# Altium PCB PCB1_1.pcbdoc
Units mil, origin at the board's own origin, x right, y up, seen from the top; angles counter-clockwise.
Board outline 1663.74 x 2242.19 mil, 2 copper layers (Top Layer, Bottom Layer); 33 components, 26 nets, 113 pads, 266 vias.
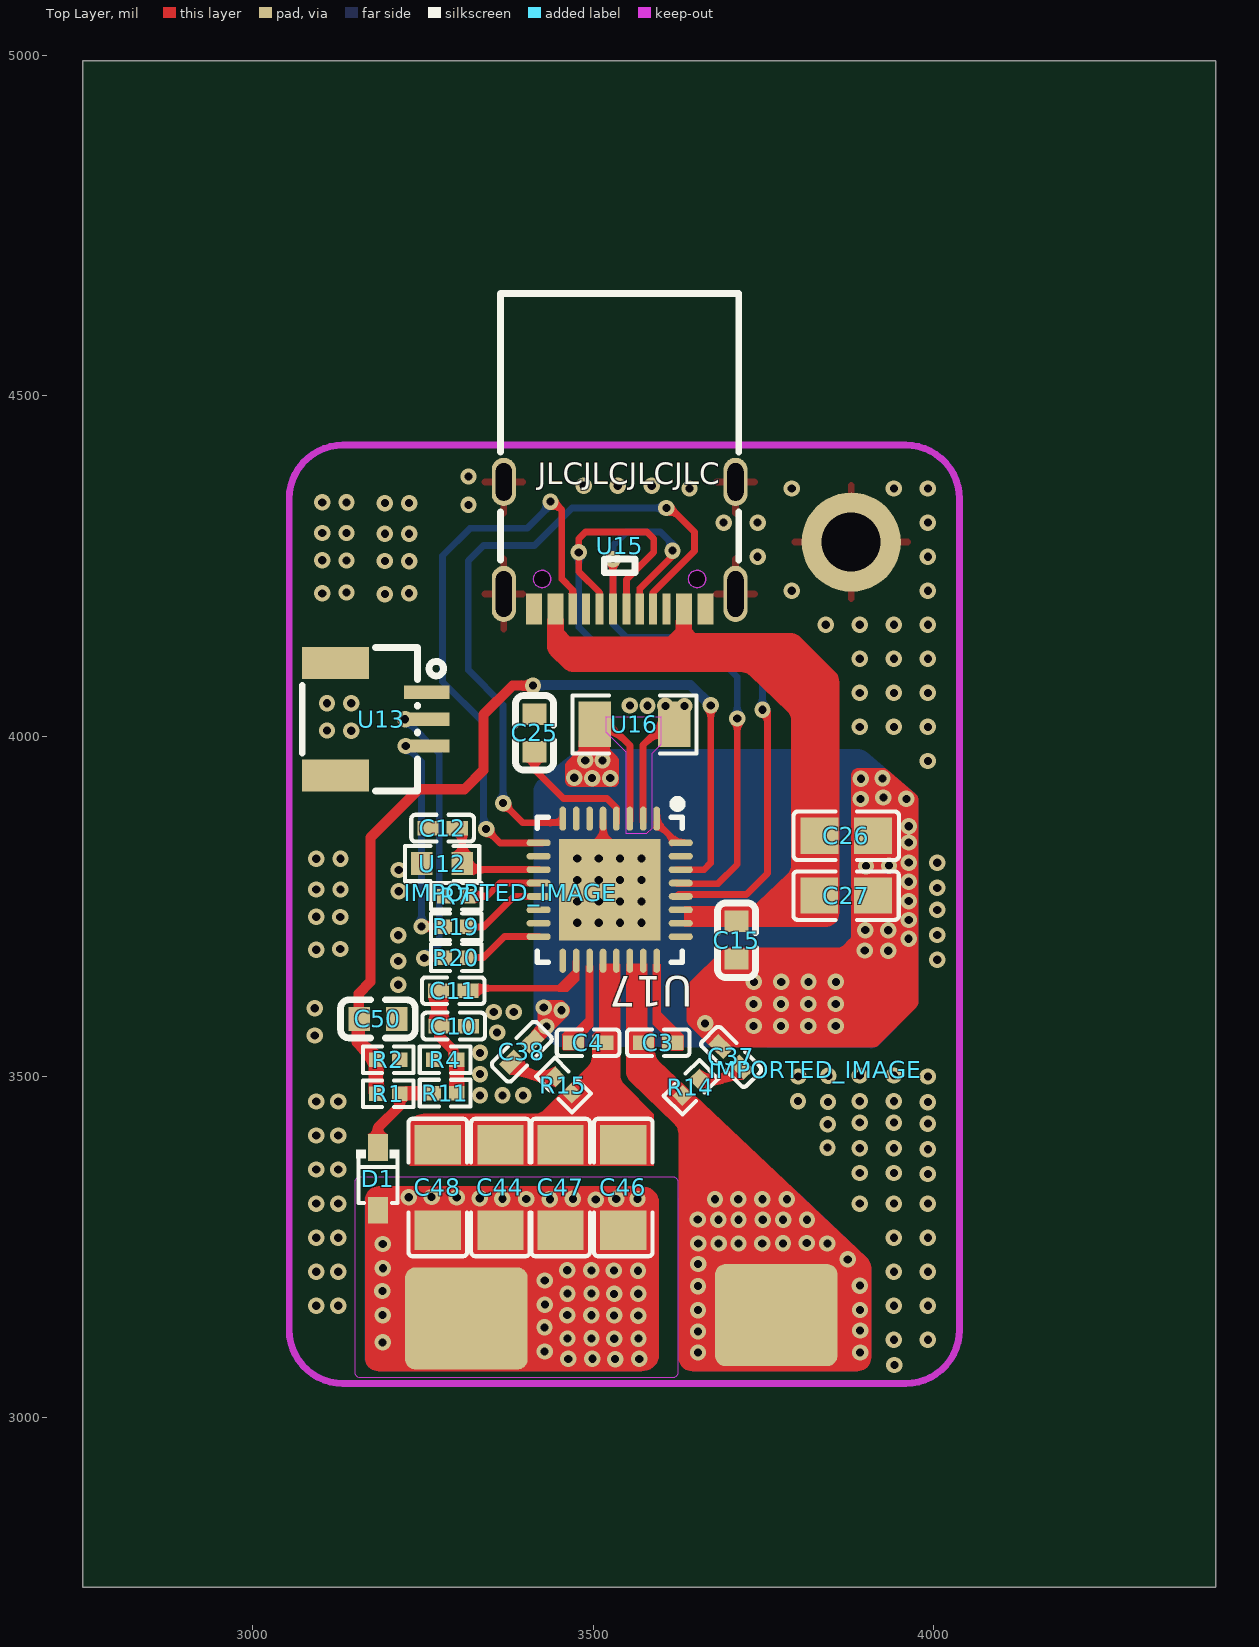
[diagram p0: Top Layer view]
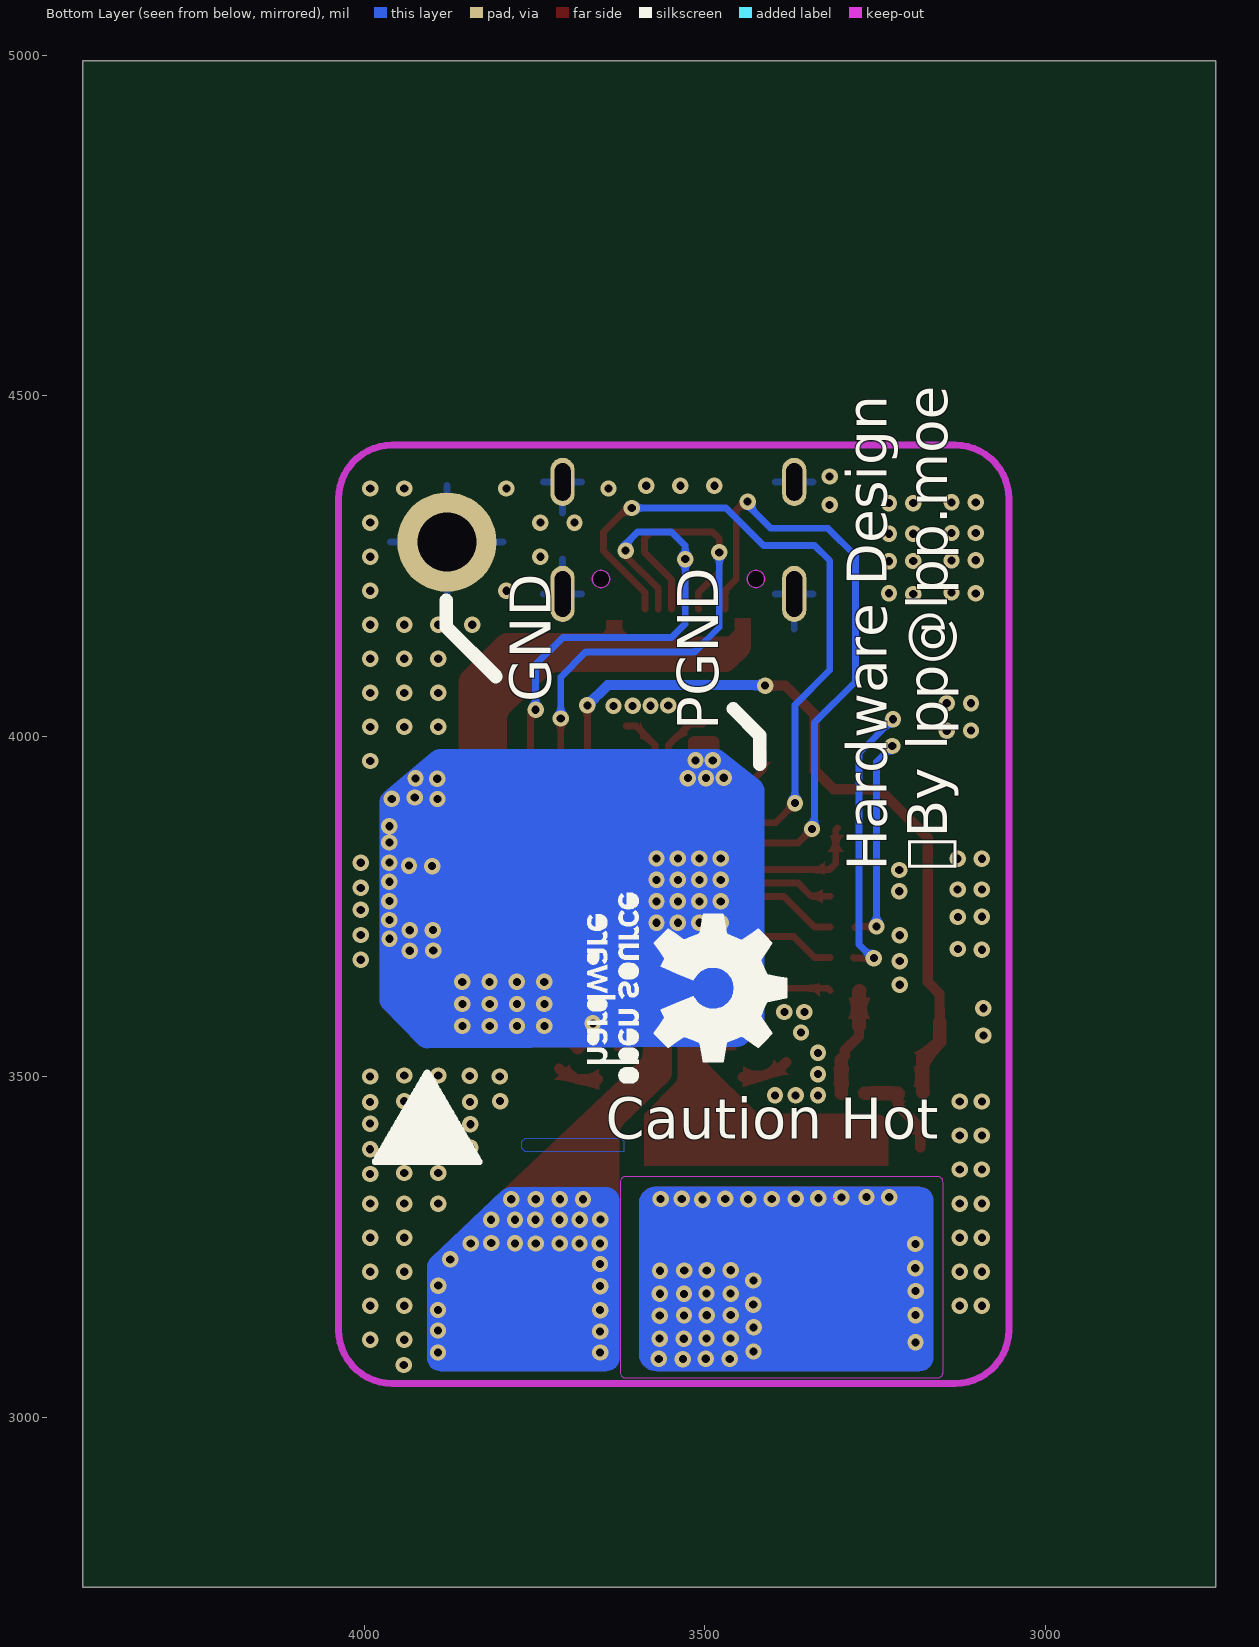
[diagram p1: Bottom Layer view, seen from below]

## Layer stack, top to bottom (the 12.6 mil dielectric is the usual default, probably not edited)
Top Layer: signal copper (thickness not stored)
Dielectric: dielectric 12.6, FR-4, Dk 4.8
Bottom Layer: signal copper (thickness not stored)

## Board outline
4413.74,2750 2750,2750 2750,4992.19 4413.74,4992.19

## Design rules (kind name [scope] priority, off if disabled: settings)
BoardOutlineClearance copperThickness1oz [All] p0: genericclearance=10 ignorepadtopadclearanceinfootprint=FALSE except(0: Arc-SplitContinuation Track-SplitContinuation SMDPad-SplitContinuation THPad-SplitContinuation Via-SplitContinuation Fill-SplitContinuation Poly-SplitContinuation Region-SplitContinuation Text-SplitContinuation; 6: Track-CutoutEdge SMDPad-CutoutEdge THPad-CutoutEdge Via-CutoutEdge Region-CutoutEdge; 11.8: Track-OutlineEdge SMDPad-OutlineEdge THPad-OutlineEdge Via-OutlineEdge Fill-OutlineEdge Region-OutlineEdge Poly-OutlineEdge Text-OutlineEdge Fill-CutoutEdge)
BoardOutlineClearance copperThickness2oz [All] p0: genericclearance=10 ignorepadtopadclearanceinfootprint=FALSE except(0: Arc-SplitContinuation Track-SplitContinuation SMDPad-SplitContinuation THPad-SplitContinuation Via-SplitContinuation Fill-SplitContinuation Poly-SplitContinuation Region-SplitContinuation Text-SplitContinuation; 6: Track-CutoutEdge SMDPad-CutoutEdge THPad-CutoutEdge Via-CutoutEdge Region-CutoutEdge; 11.8: Track-OutlineEdge SMDPad-OutlineEdge THPad-OutlineEdge Via-OutlineEdge Fill-OutlineEdge Region-OutlineEdge Poly-OutlineEdge Text-OutlineEdge Fill-CutoutEdge)
Clearance copperThickness1oz [(InNet('GND') OR InNet('VDET') OR InNet('LX2') OR InNet('LX1') OR InNet('PAD1') OR InNet('V_DECODE') OR InNet('VBUS') OR InNet('PGND') OR InNet('DP') OR InNet('DN') OR InNet('DEBUG') OR InNet('CC2') OR InNet('CC1') OR InNet('$1N1645') OR InNet('$1N1658') OR InNet('$1N1611') OR InNet('$1N1640') OR InNet('$1N1651') OR InNet('$1N1650') OR InNet('$1N1648') OR InNet('$1N1649') OR InNet('$1N1655') OR InNet('$1N6577') OR InNet('$1N6953') OR InNet('$1N16061') OR InNet('$1N16063'))] p1: gap=7 ignorepadtopadclearanceinfootprint=FALSE except(4: Track-Track; 6: Track-SMDPad SMDPad-SMDPad Track-THPad SMDPad-THPad THPad-THPad Track-Via SMDPad-Via THPad-Via Via-Via SMDPad-Fill THPad-Fill Via-Fill Fill-Fill Track-Region SMDPad-Region THPad-Region Via-Region Region-Region Track-Poly SMDPad-Poly THPad-Poly Via-Poly Fill-Poly Region-Poly Poly-Poly Track-Text SMDPad-Text THPad-Text Via-Text Fill-Text Region-Text Poly-Text Text-Text; 6.9: Track-Hole SMDPad-Hole THPad-Hole Via-Hole Fill-Hole Region-Hole Poly-Hole Text-Hole Sheet-Hole; 11.8: Track-Fill Fill-Region Track-Sheet SMDPad-Sheet THPad-Sheet Via-Sheet Fill-Sheet Region-Sheet Poly-Sheet Text-Sheet)
Clearance copperThickness2oz [All] p1: gap=7 ignorepadtopadclearanceinfootprint=FALSE except(6: Track-SMDPad SMDPad-SMDPad Track-THPad SMDPad-THPad THPad-THPad Track-Via SMDPad-Via THPad-Via Via-Via SMDPad-Fill THPad-Fill Via-Fill Fill-Fill Track-Region SMDPad-Region THPad-Region Via-Region Region-Region Track-Poly SMDPad-Poly THPad-Poly Via-Poly Fill-Poly Region-Poly Poly-Poly Track-Text SMDPad-Text THPad-Text Via-Text Fill-Text Region-Text Poly-Text Text-Text; 6.9: Track-Hole SMDPad-Hole THPad-Hole Via-Hole Fill-Hole Region-Hole Poly-Hole Text-Hole Sheet-Hole; 8: Track-Track; 11.8: Track-Fill Fill-Region Track-Sheet SMDPad-Sheet THPad-Sheet Via-Sheet Fill-Sheet Region-Sheet Poly-Sheet Text-Sheet)
DiffPairsRouting differentialPair [All] p1: maxuncoupledlength=10 minlimit=5.9843 maxlimit=5.9843 mostfreqgap=5.9843 toplayer_minwidth=5 toplayer_prefwidth=10 toplayer_maxwidth=100 bottomlayer_minwidth=5 bottomlayer_prefwidth=10 bottomlayer_maxwidth=100
PasteMaskExpansion pasteMaskExpansion [All] p1: expansion=0
PlaneConnect innerPlane [All] p1: planeconnectstyle=Relief reliefexpansion=20 reliefentries=4 reliefconductorwidth=10 reliefairgap=10
PolygonConnect copperRegion [All] p1: connectstyle=Direct reliefentries=4 reliefconductorwidth=10 polygonreliefangle="90 Angle" airgapwidth=10
RoutingVias viaSize [All] p1: viastyle="Through Hole" holewidth=12.0078 minholewidth=11.811 maxholewidth=248.0314 width=24.0158 minwidth=19.685 maxwidth=393.7008
SolderMaskExpansion solderMaskExpansion [All] p1: useseparateexpansions=TRUE expansion=2.0079 expansionbottom=2.0079
Width copperThickness1oz [All] p1: maxlimit=100 minlimit=5 preferedwidth=10
Width copperThickness2oz [All] p1: maxlimit=100 minlimit=8 preferedwidth=10

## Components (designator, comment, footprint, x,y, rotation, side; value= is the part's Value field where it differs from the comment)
C3 "CL05B104KB54PNC" C0402 3595.31,3549.94 r180 top
C4 "CL05B104KB54PNC" C0402 3492.34,3549.89 r0 top
C10 "CC0402KRX7R9BB153" C0402 3295.08,3574.39 r180 top
C11 "CC0402KRX7R9BB153" C0402 3294.36,3626.34 r180 top
C12 "CC0402KRX7R9BB153" C0402 3278.74,3865 r180 top
C15 "CC0603KRX7R9BB104" C0603 3710.38,3700.45 r90 top
C25 "CL10A225KO8NNNC" C0603 3413.74,4005 r270 top
C26 "CL21A226MAQNNNE" C0805 3871.51,3853.83 r180 top
C27 "CL21A226MAQNNNE" C0805 3871.27,3765.98 r180 top
C37 "CC0402JRX7R9BB222" C0402 3702.44,3529.14 r135 top
C38 "CC0402JRX7R9BB222" C0402 3395.06,3536.66 r45 top
C44 "GRM31M5C1H473JA01L" C1206 3363.74,3337.35 r270 top
C46 "GRM31C5C1H104JA01L" C1206 3544.11,3337.35 r270 top
C47 "GRM31C5C1H104JA01L" C1206 3451.95,3337.35 r270 top
C48 "GRM31C5C1H104JA01L" C1206 3271.74,3337.35 r270 top
C50 "0603B222K500NT" C0603 3183.74,3585 r0 top
D1 "1N5819WS_C191023" SOD-323_L1.8-W1.3-LS2.5-RD 3183.74,3350 r270 top
IMPORTED_IMAGE "IMPORTED_IMAGE" IMPORTED_IMAGE 3379.02,3770.18 r0 top
IMPORTED_IMAGE "IMPORTED_IMAGE" IMPORTED_IMAGE 3826.97,3510.36 r0 top
R1 "0402WGF1003TCE" R0402 3198.74,3475 r0 top
R2 "0402WGF1002TCE" R0402 3198.74,3525 r180 top
R4 "0402WGF3302TCE" R0402 3282.36,3524.96 r0 top
R7 "0402WGF1003TCE" R0402 3298.74,3765 r180 top
R11 "0402WGF3301TCE" R0402 3282.36,3475.9 r0 top
R14 "0402WGF200KTCE" R0402 3643.28,3484.41 r45 top
R15 "0402WGF200KTCE" R0402 3456.27,3487.73 r135 top
R19 "0402WGF1000TCE" R0402 3298.74,3720 r0 top
R20 "0402WGF1000TCE" R0402 3298.74,3675 r0 top
U12 "KNTC0603/100KF3950" R0603 3278.05,3813.05 r0 top
U13 "WAFER-SH1.0-3PWB" CONN-SMD_3P-P1.00_WAFER-SH1.0-3PWB 3188.74,4025 r270 top
U15 "MC-121-L119" USB-C-SMD_HANBO_MC-121-L119 3538.74,4280 r180 top
U16 "FRM121WFR020TM" R1206 3560.49,4017.39 r0 top
U17 "IP6826_C2921390" QFN-32_L5.0-W5.0-P0.50-BL-EP3.8 3524.15,3774.57 r180 top

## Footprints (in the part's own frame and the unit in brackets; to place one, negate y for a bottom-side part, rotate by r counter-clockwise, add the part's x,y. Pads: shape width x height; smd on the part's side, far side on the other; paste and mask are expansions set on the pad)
C0402 [mm]
  rect 0.79x0.54 smd: 1(-0.545,0) 2(0.545,0)
  silkscreen extent -1.17,-0.5 1.17,0.5
C0603 [mm]
  rect 0.8x0.9 smd: 1(-0.7,0) 2(0.7,0)
  silkscreen extent -1.39,-0.71 1.39,0.71
C0805 [mm]
  rect 1.41x1.35 smd: 1(-1,0) 2(1,0)
  silkscreen extent -1.96,-0.9 1.96,0.9
C1206 [mm]
  rect 1.485x1.728 smd: 1(-1.593,0) 2(1.593,0)
  silkscreen extent -2.56,-1.09 2.56,1.09
CONN-SMD_3P-P1.00_WAFER-SH1.0-3PWB [mm]
  rect 0.5x1.7 smd: 1(-1,1.7) 2(0,1.7) 3(1,1.7)
  rect 1.2x2.5 smd: 4(-2.1,-1.7) 5(2.1,-1.7)
  silkscreen extent -2.68,-2.95 2.67,2.32
IMPORTED_IMAGE [mil]
QFN-32_L5.0-W5.0-P0.50-BL-EP3.8 [mm]
  oval 0.25x0.9 smd: 1(-1.75,-2.65) 2(-1.25,-2.65) 3(-0.749,-2.65) 4(-0.249,-2.65) 5(0.249,-2.65) 6(0.749,-2.65) 7(1.25,-2.65) 8(1.75,-2.65) 17(1.75,2.65) 18(1.25,2.65) 19(0.749,2.65) 20(0.249,2.65) 21(-0.249,2.65) 22(-0.749,2.65) 23(-1.25,2.65) 24(-1.75,2.65)
  oval 0.9x0.25 smd: 9(2.65,-1.75) 10(2.65,-1.25) 11(2.65,-0.749) 12(2.65,-0.249) 13(2.65,0.249) 14(2.65,0.749) 15(2.65,1.25) 16(2.65,1.75) 25(-2.65,1.75) 26(-2.65,1.25) 27(-2.65,0.749) 28(-2.65,0.249) 29(-2.65,-0.249) 30(-2.65,-0.749) 31(-2.65,-1.25) 32(-2.65,-1.75)
  rect 3.8x3.8 smd: 33(0,0)
  silkscreen extent -2.7,-3.35 2.7,2.7
R0402 [mm]
  rect 0.566x0.54 smd: 1(-0.433,0) 2(0.433,0)
  silkscreen extent -0.94,-0.5 0.94,0.5
R0603 [mil]
  rect 31.75x34.02 smd: 1(-29.66,0) 2(29.66,0)
  silkscreen extent -55,-26 55,26
R1206 [mil]
  rect 47.54x66.97 smd: 1(-58.22,0) 2(58.22,0)
  silkscreen extent -91,-42 91,42
SOD-323_L1.8-W1.3-LS2.5-RD [mm]
  rect 1x0.75 smd: 1(-1.173,0) 2(1.173,0)
  silkscreen extent -1.08,-0.8 0.9,0.8
USB-C-SMD_HANBO_MC-121-L119 [mm]
  oval 0.9x1.8 hole 0.6 slot 1.4 at 90 deg: 13(-4.32,-2.373) 13(4.32,-2.373)
  oval 0.9x2.1 hole 0.6 slot 1.7 at 90 deg: 13(-4.32,1.807) 13(4.32,1.807)
  rect 0.6x1.15 smd: A1B12(-3.2,2.372) A4B9(-2.4,2.372) B1A12(3.2,2.372) B4A9(2.4,2.372)
  rect 0.3x1.15 smd: A5(-1.25,2.372) A6(-0.25,2.372) A7(0.25,2.372) A8(1.25,2.372) B5(1.75,2.372) B6(0.75,2.372) B7(-0.75,2.372) B8(-1.75,2.372)
  Board Outline Layer circle w0.005: c2.89,1.248 r0.325
  Board Outline Layer circle w0.005: c-2.89,1.248 r0.325
  Board Outline Layer region: 2.565,1.248 2.597,1.389 2.687,1.502 2.818,1.564 2.962,1.564 3.093,1.502 3.183,1.389 3.215,1.248 3.215,1.248 3.183,1.107 3.093,0.993 2.962,0.931 2.818,0.931 2.687,0.993 2.597,1.107 2.565,1.248
  Board Outline Layer region: -3.215,1.248 -3.183,1.389 -3.093,1.502 -2.962,1.564 -2.818,1.564 -2.688,1.502 -2.597,1.389 -2.565,1.248 -2.565,1.248 -2.597,1.107 -2.688,0.993 -2.818,0.931 -2.962,0.931 -3.093,0.993 -3.183,1.107 -3.215,1.248
  Multi-Layer board cut-out: 2.565,1.248 2.597,1.389 2.687,1.502 2.818,1.564 2.962,1.564 3.093,1.502 3.183,1.389 3.215,1.248 3.215,1.248 3.183,1.107 3.093,0.993 2.962,0.931 2.818,0.931 2.687,0.993 2.597,1.107 2.565,1.248
  Multi-Layer board cut-out: -3.215,1.248 -3.183,1.389 -3.093,1.502 -2.962,1.564 -2.818,1.564 -2.688,1.502 -2.597,1.389 -2.565,1.248 -2.565,1.248 -2.597,1.107 -2.688,0.993 -2.818,0.931 -2.962,0.931 -3.093,0.993 -3.183,1.107 -3.215,1.248
  silkscreen extent -4.45,-9.4 4.44,1.02

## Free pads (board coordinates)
  rrect20% 180x150 smd: 1(3313.74,3145) 1(3768.74,3150)
  round 145.67 hole 86.61: 1(3878.74,4285)

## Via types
v1: diameter 24.02, hole 12.01, Top Layer to Bottom Layer, 266 vias

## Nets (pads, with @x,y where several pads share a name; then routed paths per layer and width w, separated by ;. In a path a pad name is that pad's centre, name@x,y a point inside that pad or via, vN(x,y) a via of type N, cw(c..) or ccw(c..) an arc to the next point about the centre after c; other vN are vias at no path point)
$1N1611: C25.2 U17.4 | length 191.8
  Top Layer w10: C25.2 3413.74,3951.14 3456.19,3908.69 3520.05,3908.69 3534.02,3894.72 U17.4@3534.02,3872.91
$1N1640: D1.1 R1.2 R11.1 | length 142
  Top Layer w15: D1.1 3183.74,3425 3215.78,3457.04 R1.2
  Top Layer w20: R1.2 3216.68,3475.9 R11.1
$1N1645: C10.2 C11.2 R4.2 R11.2 | length 161.4
  Top Layer w15: C10.2 3273.62,3559.39 3294.4,3538.6 3294.4,3529.96 R4.2
  Top Layer w20: C11.2 3273.62,3625.61 C10.2 ; R11.2 R4.2
$1N1648: R19.2 U17.13 | length 122.6
  Top Layer w10: R19.2 3338.97,3720 3383.74,3764.77 U17.13
$1N1649: R20.2 U17.16 | length 116.7
  Top Layer w10: R20.2 3338.74,3675 3369.41,3705.67 U17.16
$1N1650: R19.1 U13.3 | length 306.9
  Top Layer w10: v1(3247.82,3720.58) 3278.3,3720.58 R19.1@3279.54,3719.34
  Bottom Layer w10: v1(3224.71,3985.64) 3247.82,3962.52 v1(3247.82,3720.58)
$1N1651: R20.1 U13.2 | length 412.3
  Top Layer w10: v1(3251.71,3674.12) 3280.82,3674.12 R20.1
  Bottom Layer w10: v1(3223.67,4025) 3273.74,3975 3273.74,3694.05 3253.81,3674.12 v1(3251.71,3674.12)
$1N1655: R7.1 U17.12 | length 112.1
  Top Layer w10: R7.1 3343.74,3765 3363.11,3784.37 U17.12
$1N1658: C12.1 U12.2 U17.11 | length 168.8
  Top Layer w10: C12.1@3305.2,3865 3307.71,3862.49 U12.2 3316.69,3804.07 U17.11
$1N6577: C37.1 R14.2 | length 61.7
  Top Layer w15: R14.2@3656.93,3496.23 ccw(c3671.11,3554.9) C37.1@3713.79,3512.22
$1N6953: C38.1 R15.2 | length 70.3
  Top Layer w15: C38.1 ccw(c3433.96,3575.56) R15.2
$1N16061: C3.1 U17.24
$1N16063: C4.1 U17.19
CC1: U15.A5 U17.8 | length 994.3
  Top Layer w10: v1(3367.62,3901.73) 3396.52,3872.83 U17.8@3455.17,3872.83 ; U15.A5 3587.66,4186.89 3587.66,4210.69 3648.74,4271.78 3648.74,4300 3613.65,4335.09 v1(3607.28,4335.09)
  Bottom Layer w10: v1(3367.62,3901.73) 3367.62,4046.12 3316.52,4097.22 3316.52,4257.78 3338.74,4280 3413.74,4280 3468.83,4335.09 v1(3607.28,4335.09)
CC2: U15.B5 U17.9 | length 887.3
  Top Layer w10: v1(3342.6,3863.81) 3363.1,3843.31 U17.9@3425.65,3843.31 ; v1(3437.16,4344.52) 3441.27,4344.52 3453.74,4332.05 3453.74,4231.01 3469.85,4214.9 U15.B5
  Bottom Layer w10: v1(3342.6,3863.81) 3338.74,3867.67 3338.74,4020 3278.74,4080 3278.74,4265 3319.04,4305.3 3402.95,4305.3 3437.16,4339.52 v1(3437.16,4344.52)
DEBUG: U17.10
DN: U15.A7 U15.B7 U17.28 | length 1108.6
  Top Layer w10: v1(3528.74,4260) 3528.9,4259.85 U15.A7 ; U15.B7 3568.27,4216.92 3616.24,4264.9 v1(3616.24,4272.5) ; U17.28@3622.6,3764.64 3625.4,3767.44 3724.67,3767.44 3755.88,3798.65 3755.88,4031.3 v1(3748.41,4038.77)
  Bottom Layer w10: v1(3616.24,4272.5) 3616.24,4282.5 3598.74,4300 3548.74,4300 3528.74,4280 v1(3528.74,4260) 3528.74,4165 3548.74,4145 3708.39,4145 3748.41,4104.98 v1(3748.41,4038.77)
DP: U15.A6 U15.B6 U17.29 | length 1103.8
  Top Layer w10: U15.B6 3509.5,4186.88 3509.5,4210.69 3478.74,4241.46 v1(3478.74,4270) 3478.74,4290 3488.74,4300 3578.74,4300 3588.74,4290 3588.74,4270 3548.74,4230 3548.74,4186.75 U15.A6 ; U17.29@3622.49,3784.25 3623.32,3783.42 3682.91,3783.42 3711.43,3811.94 v1(3711.43,4025.98)
  Bottom Layer w10: v1(3478.74,4270) 3478.74,4160 3515.25,4123.49 3675.09,4123.49 3711.43,4087.15 v1(3711.43,4025.98)
GND: C10.1 C12.2 C25.1 C50.2 pad.1@3878.74,4285 R2.1 R4.1 R7.2 U12.1 U13.1 U13.4 U13.5 U15.13 U15.A1B12 U15.B1A12 U16.2 U17.1 U17.2 U17.32 | length 209.7
  Top Layer w10: U17.2@3573.04,3874.52 3573.04,3986.97 3601.08,4015 U16.2@3615.22,4015 ; U17.1@3593.21,3873.46 3623.14,3843.54 U17.32@3624.24,3843.54
  other v1: 3942.14,3076.61 3941.37,3113.66 3991.37,3113.66 3093.18,3163.66 3125.57,3163.66 3941.37,3163.66 3991.37,3163.66 3093.18,3213.66 3125.57,3213.66 3941.37,3213.66 3991.37,3213.66 3093.18,3263.66 3125.57,3263.66 3941.37,3263.66 3991.37,3263.66 3093.18,3313.66 3125.57,3313.66 3891.37,3313.66 3941.37,3313.66 3991.37,3313.66 3991.39,3357.16 3891.37,3358.57 3941.37,3358.57 3093.18,3363.66 3125.57,3363.66 3991.39,3393.49 3891.37,3394.9 3941.37,3394.9 3843.95,3395.95 3093.18,3413.66 3125.57,3413.66 3844.22,3430.17 3991.39,3431.14 3891.37,3432.54 3941.37,3432.54 3844.68,3462.81 3991.39,3462.69 3093.18,3463.66 3125.57,3463.66 3800.53,3464.17 3891.37,3464.1 3941.37,3464.1 3333.74,3472.55 3366.6,3472.55 3396.95,3472.55 3801.07,3500.41 3991.39,3500.34 3845.22,3501.23 3891.37,3501.74 3941.37,3501.74 3333.74,3503.84 3333.74,3535 3090.95,3560.54 3358.74,3565 3353.74,3595 3383.18,3595 3090.95,3600.54 3213.74,3635 3213.74,3669.75 4005.13,3671.8 3093.18,3686.35 3128.33,3687.58 3213.74,3707.6 4005.13,3708.13 3093.18,3735 3128.33,3734.59 4005.13,3744.96 3214.36,3772.41 3093.18,3775 3128.74,3775 4005.13,3777.33 3214.36,3803.47 4005.13,3814.16 3093.18,3820 3128.74,3820 3991.37,3963.66 3109.01,4008.48 3144.58,4008.07 3891.37,4013.66 3941.37,4013.66 3991.37,4013.66 3634.04,4044.27 3553.74,4045 3579.69,4044.7 3605.92,4044.6 3109.01,4048.48 3144.58,4048.48 3891.37,4063.66 3941.37,4063.66 3991.37,4063.66 3891.37,4113.66 3941.37,4113.66 3991.37,4113.66 3841.37,4163.66 3891.37,4163.66 3941.37,4163.66 3991.37,4163.66 3193.96,4208.67 3102.09,4209.72 3229.52,4209.89 3137.66,4210.95 3791.37,4213.66 3991.37,4213.66 3193.96,4257.32 3229.52,4256.91 3102.09,4258.37 3137.66,4257.96 3741.37,4263.66 3991.37,4263.66 3193.96,4297.32 3229.52,4297.32 3102.09,4298.37 3137.66,4298.37 3691.37,4313.66 3741.37,4313.66 3991.37,4313.66 3316.76,4339.73 3193.96,4342.32 3229.52,4342.32 3102.09,4343.37 3137.66,4343.37 3641.37,4363.66 3791.37,4363.66 3941.37,4363.66 3991.37,4363.66 3485.88,4367.84 3535.88,4367.84 3585.88,4367.84 3316.76,4381.42
LX1: C4.2 C44.1 C46.1 C47.1 C48.1 R15.1 U17.20 U17.21
LX2: C3.2 pad.1@3768.74,3150 R14.1 U17.22 U17.23
  other v1: 3653.74,3095 3891.82,3094.99 3653.74,3125.86 3891.82,3127.28 3653.74,3157.34 3891.66,3157.48 3653.74,3192.5 3891.49,3193.23 3653.88,3224.99 3873.65,3231.73 3654.1,3255.09 3684.01,3255 3713.18,3255 3748.1,3255 3778.63,3255.27 3843.74,3255 3813.49,3255.82 3653.29,3290.35 3683.74,3290 3713.18,3290 3748.74,3290 3778.74,3290 3813.74,3290 3678.74,3320 3712.75,3320 3748.31,3320 3784.28,3320
PAD1: C44.2 C46.2 C47.2 C48.2 D1.2 pad.1@3313.74,3145
  other v1: 3532.13,3085.34 3463.27,3085.7 3498.7,3085.97 3567.55,3085.61 3428.57,3096.44 3190.63,3109.89 3530.9,3115.18 3566.33,3115.45 3462.04,3115.54 3497.47,3115.82 3428.29,3131.87 3566.06,3149.25 3190.65,3149.99 3461.77,3149.88 3497.2,3149.61 3530.63,3149.52 3428.93,3165.3 3462.04,3181.49 3530.54,3181.13 3565.96,3181.4 3497.47,3181.77 3190.38,3185.42 3428.66,3200.73 3530.26,3215.47 3565.69,3215.2 3461.77,3215.83 3497.2,3215.56 3191.01,3218.85 3190.74,3254.28 3401.63,3320.39 3436.24,3320.12 3503.56,3319.58 3564.87,3320.39 3333.23,3321.48 3366.47,3320.94 3470.03,3320.67 3533.81,3320.67 3229.12,3323.12 3262.64,3323.39 3299.43,3322.57
PGND: C15.1 C26.1 C27.1 C37.2 C38.2 U16.1 U17.3 U17.5 U17.33 | length 220.1
  Top Layer w10: U16.1@3502.56,4018.16 3521.76,4018.16 3553.74,3986.18 3553.74,3875.9 U17.3@3553.66,3875.82 ; U17.33@3514.47,3829.89 U17.5@3514.47,3875.12
  other v1: 3431.15,3573.84 3735.5,3574.49 3775.65,3574.49 3815.8,3574.49 3855.95,3574.49 3664.26,3578.35 3453.26,3597.47 3427.22,3601.66 3735.5,3606.85 3775.65,3606.85 3815.8,3606.85 3855.95,3606.85 3735.82,3639.21 3775.96,3639.21 3816.11,3639.21 3856.26,3639.21 3898.74,3685.41 3933.23,3685.04 3963.05,3702.67 3899.25,3715.27 3933.22,3714.96 3476.47,3726 3507.97,3726 3539.46,3726 3570.96,3726 3963.17,3730.15 3476.47,3757.49 3507.97,3757.49 3539.46,3757.49 3570.96,3757.49 3963.17,3757.83 3963.17,3786.28 3476.47,3788.99 3507.97,3788.99 3539.46,3788.99 3570.96,3788.99 3900.41,3809.29 3934.31,3809.94 3963.17,3814.34 3476.47,3820.49 3507.97,3820.49 3539.46,3820.49 3570.96,3820.49 3963.17,3843.94 3963.17,3867.78 3892.59,3907.8 3959.73,3907.97 3925.99,3909.96 3892.9,3937.52 3924.74,3938.12 3472.18,3939.03 3498.25,3938.51 3524.82,3938.51 3488.24,3964.55 3513.54,3964.55
V_DECODE: C11.1 U17.18 | length 145.7
  Top Layer w10: C11.1 3319.4,3629.93 3459.98,3629.93
VBUS: C15.2 C26.2 C27.2 U15.A4B9 U15.B4A9 U17.26 U17.27
VDET: C50.1 R1.1 R2.2 U17.30 | length 1327.2
  Top Layer w10: U17.30@3622.49,3803.94 3662.68,3803.94 3672.44,3813.7 v1(3672.44,4045.24)
  Top Layer w15: C50.1@3155.1,3579.96 3155.51,3622.06 3172.68,3639.23 3172.68,3850.98 3243.8,3922.11 3310.85,3922.11 3338.64,3949.91 3338.64,4031.51 3381.47,4074.33 v1(3411.39,4074.33)
  Top Layer w20: C50.1@3155.1,3579.95 3155.1,3551.34 R2.2@3179.62,3526.81 ; R1.1@3179.62,3477.35 3180.03,3477.76 R2.2@3180.03,3524.77
  Bottom Layer w15: v1(3411.39,4074.33) 3412.06,4075 3642.68,4075 v1(3672.44,4045.24)
pads on no net: U15.A8 U15.B8 U17.6 U17.7 U17.14 U17.15 U17.17 U17.25 U17.31

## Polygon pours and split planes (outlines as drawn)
GND on Top Layer (solid, remove dead copper, pour order 0): 3000.36,4742.19 4085.79,4742.19 4085.79,3004.55 3000.36,3004.55
GND on Bottom Layer (solid, remove dead copper, pour order 2): 3000,4453.45 4163.74,4453.45 4163.74,3000 3000,3000
LX2 on Bottom Layer (solid, remove dead copper, pour order 4): 3618.74,3405 3618.74,3390 3763.74,3390 3768.74,3395 3768.74,3405 3763.74,3410 3623.74,3410

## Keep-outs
Top Layer:
  region: 3518.3,4027.93 3518.3,4006.75 3547.98,3977.08 3547.98,3857.16 3578.86,3857.16 3586.37,3864.67 3586.37,3974.84 3599.76,3988.22 3599.76,4028.11
Bottom Layer:
  region: 3313.06,3320.99 3313.87,3321.8 3309.81,3321.8 3309,3320.99
Board Outline Layer:
  region: 3158,3353.15 3616.25,3353.15 cw(c3616.25,3345.27) 3624.12,3345.27 3624.12,3065.66 cw(c3616.25,3065.66) 3616.25,3057.78 3158,3057.78 cw(c3158,3065.66) 3150.12,3065.66 3150.12,3345.27 cw(c3158,3345.27)
  lines w10: 3053.49,3128.3 ccw(c3132.23,3128.3) 3132.23,3049.56 3959.01,3049.56 ccw(c3959.01,3128.3) 4037.75,3128.3 4037.75,4348.77 ccw(c3959.01,4348.77) 3959.01,4427.51 3132.23,4427.51 ccw(c3132.23,4348.77) 3053.49,4348.77 3053.49,3128.3

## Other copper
Top Layer:
  region net $1N16061: 3587.26,3665.45 3587.26,3577.18 3600.77,3563.68 3600.77,3539.43 3601.89,3538.31 3631.69,3538.31 3632.76,3539.38 3632.76,3560.9 3598.8,3594.86 3598.8,3665.45
  region net $1N16063: 3500.25,3663.25 3500.25,3574.16 3486.58,3560.5 3486.58,3540.21 3485.09,3538.71 3455.83,3538.71 3454.12,3540.42 3454.12,3561.35 3453.91,3561.56 3463.3,3570.96 3474.2,3570.96 3489.27,3586.03 3489.27,3663.25
  region net LX1: 3508.92,3665.79 3508.92,3571.31 3498.17,3560.56 3498.17,3529.45 cw(c3478.48,3529.45) 3492.4,3515.53 3428.04,3451.17 cw(c3414.12,3465.08) 3414.12,3445.4 3250.02,3445.4 ccw(c3250.02,3425.71) 3230.34,3425.71 3230.34,3369.01 3230.34,3369 3589.09,3369 3589.11,3368.99 3589.11,3445.21 3589.12,3445.22 3545.24,3489.1 cw(c3559.16,3503.02) 3539.48,3503.02 3539.48,3665.16 3538.81,3665.83 3508.97,3665.83
  region net LX2: 3888.13,3067.65 3644.97,3067.65 cw(c3644.97,3087.33) 3625.28,3087.33 3625.28,3416.39 ccw(c3605.6,3416.39) 3619.24,3430.58 3553.96,3493.34 cw(c3567.87,3507.26) 3548.19,3507.26 3548.17,3665.84 3548.24,3665.91 3579.1,3665.91 3579.1,3573.06 3590.61,3561.55 3590.61,3536.52 ccw(c3610.29,3536.52) 3596.37,3522.6 3901.64,3234.42 cw(c3888.13,3220.1) 3907.82,3220.1 3907.82,3087.33 cw(c3888.13,3087.33)
  region net PGND: 3478.82,3991.84 3478.76,3983.23 cw(c3470.89,3983.28) 3476.46,3977.72 3461.05,3962.31 ccw(c3466.61,3956.74) 3458.74,3956.74 3458.74,3935.42 ccw(c3468.59,3935.15) 3466.61,3925.5 3529.88,3925.5 ccw(c3529.35,3933.89) 3537.75,3933.97 3537.75,3963.94 ccw(c3529.88,3963.94) 3535.45,3969.51 3526.38,3978.57 cw(c3531.95,3984.14) 3524.08,3984.14 3524.08,3991.79 ccw(c3516.2,3991.79) 3516.2,3999.66 3486.69,3999.66 ccw(c3486.69,3991.79)
  region net PAD1: 3184.01,3067.82 3570.84,3067.82 ccw(c3571.78,3092.85) 3596.25,3087.5 3596.25,3319.22 ccw(c3571.6,3313.63) 3570.84,3338.9 3184.61,3338.9 ccw(c3184.61,3319.22) 3164.93,3319.22 3164.93,3087.5 ccw(c3184.1,3087)
  region net VBUS: 3735.44,3719.92 3633.27,3719.92 3633.27,3750.39 3727.74,3750.39 ccw(c3727.74,3770.39) 3741.59,3755.95 3784.71,3797.3 ccw(c3770.87,3811.74) 3790.87,3811.74 3790.87,4022.18 ccw(c3770.87,4022.18) 3784.72,4036.6 3730.28,4088.87 ccw(c3716.43,4074.44) 3716.43,4094.44 3470.52,4094.44 cw(c3470.52,4114.44) 3456.38,4100.3 3438.19,4118.49 cw(c3452.33,4132.63) 3432.33,4132.63 3432.33,4172.23 3433.2,4173.1 3455.78,4173.1 3456.32,4172.56 3456.32,4155.47 3465.78,4146.01 3610.15,4146.01 3621.35,4157.2 3621.35,4169.85 3621.45,4169.96 3644.16,4169.96 3644.81,4169.31 3644.81,4156.71 3650.05,4151.47 3789.61,4151.47 cw(c3789.61,4131.47) 3803.75,4145.61 3855.11,4094.25 cw(c3840.97,4080.11) 3860.97,4080.11 3860.97,3739.92 cw(c3840.97,3739.92) 3840.97,3719.92
  region net V_DECODE: 3470.02,3670.24 3470.02,3656.03 3448.74,3634.75 3448.74,3625.03 3462.74,3625.03 3479.7,3641.99 3479.7,3670.24
  region net PGND: 3878.98,3708.68 3878.98,3943.19 cw(c3888.98,3943.19) 3888.95,3953.19 3924.99,3953.28 cw(c3925.02,3943.28) 3931.51,3950.88 3973.64,3914.9 cw(c3967.15,3907.29) 3977.15,3907.29 3977.15,3897.18 3977.07,3897.09 3977.07,3725 3977.1,3609.11 cw(c3967.1,3609.11) 3974.17,3602.04 3918.21,3546.08 cw(c3911.13,3553.15) 3911.13,3543.15 3698.26,3543.15 cw(c3690.59,3544.97) 3696.16,3539.4 3692.15,3535.38 cw(c3686.58,3540.95) 3686.58,3533.08 cw(c3686.58,3540.95) 3681.01,3535.38 3673.25,3543.15 3640.4,3575.94 cw(c3647.47,3583.02) 3637.47,3583.02 3637.47,3630.01 cw(c3647.47,3630.01) 3640.4,3637.08 3689.86,3686.54 cw(c3696.93,3679.47) 3696.93,3689.47 3859.76,3689.47 ccw(c3859.76,3699.47) 3866.84,3692.4 3876.05,3701.61 ccw(c3868.98,3708.68)
  region net PGND: 3418.18,3604.73 3418.16,3578.93 cw(c3410.29,3578.93) 3415.85,3573.36 3411.06,3568.57 ccw(c3416.62,3563) 3411.06,3557.43 3415.07,3553.42 ccw(c3420.64,3558.99) 3426.21,3553.42 3463.38,3590.59 ccw(c3457.81,3596.16) 3465.69,3596.16 3465.69,3598.95 ccw(c3457.81,3598.95) 3463.38,3604.52 3457.61,3610.29 ccw(c3452.04,3604.72) 3452.04,3612.6 3426.05,3612.6 ccw(c3426.05,3604.72)
  region net $1N1645: 3263.62,3615.01 3283.62,3615.01 ccw(c3367.43,3615.01) 3289.17,3585.01 3258.07,3585.01 ccw(c3179.81,3615.01)
  region net $1N1645: 3283.62,3585.71 3263.62,3585.71 ccw(c3188.81,3585.71) 3257.34,3615.71 3288.45,3615.71 ccw(c3379.25,3585.71)
  region net V_DECODE: 3346.37,3634.93 3346.37,3624.93 ccw(c3346.37,3606.18) 3331.37,3617.43 3331.37,3636.97 ccw(c3346.37,3691.08)
  region net $1N1658: 3312.71,3839.37 3302.71,3839.37 ccw(c3283.96,3839.37) 3295.21,3854.37 3315.75,3854.37 ccw(c3351.17,3839.37)
  region net $1N1640: 3176.24,3425 3191.24,3425 ccw(c3200.64,3425) 3198.5,3415.85 3168.98,3415.85 ccw(c3166.85,3425)
  region net $1N1640: 3223.28,3457.04 3208.28,3457.04 ccw(c3199.07,3457.04) 3204.65,3464.37 3226.92,3464.37 ccw(c3232.49,3457.04)
  region net $1N1640: 3256.92,3485.9 3256.92,3465.9 ccw(c3256.92,3171.61) 3226.92,3464.37 3226.92,3485.63 ccw(c3226.91,5133.57)
  region net VDET: 3170.03,3515.63 3190.03,3515.63 ccw(c3352.03,3515.63) 3192.84,3485.63 3170.57,3485.63 ccw(c2324.44,3485.63)
  region net VDET: 3190.03,3484.37 3170.03,3484.37 ccw(c2324.44,3514.37) 3170.57,3514.37 3192.84,3514.37 ccw(c3352.03,3484.37)
  region net VDET: 3153.03,3539.26 3167.68,3552.9 ccw(c3226.7,3611.92) 3192.84,3535.63 3170.57,3514.37 ccw(c3090.03,3476.26)
  region net $1N1645: 3309.4,3484.33 3289.4,3484.33 ccw(c2892.36,3484.33) 3288.27,3514.33 3310.54,3514.33 ccw(c3706.45,3484.33)
  region net $1N1655: 3341.92,3770 3341.92,3760 ccw(c3341.92,3737.2) 3326.92,3754.37 3326.92,3775.63 ccw(c3341.92,3792.8)
  region net $1N1658: 3338.58,3809.07 3338.58,3799.07 ccw(c3338.58,3760.43) 3323.58,3796.04 3323.58,3816.57 ccw(c3338.58,3827.82)
  region net $1N1658: 3302.71,3845.06 3312.71,3845.06 ccw(c3331.46,3845.06) 3320.21,3830.06 3295.21,3830.06 ccw(c3283.96,3845.06)
  region net $1N1611: 3418.74,3951.14 3408.74,3951.14 ccw(c3397.56,3951.14) 3401.24,3961.69 3426.24,3961.69 ccw(c3429.92,3951.14)
  region net $1N1645: 3289.4,3516.53 3309.4,3516.53 ccw(c3706.45,3516.53) 3310.54,3486.53 3288.27,3486.53 ccw(c2892.36,3516.53)
  region net $1N1640: 3224.19,3465.9 3224.19,3485.9 ccw(c3224.19,4200.49) 3254.19,3486.53 3254.19,3465.27 ccw(c3224.19,2751.31)
  region net CC2: 3464.85,4214.9 3474.85,4214.9 ccw(c3493.04,4214.9) 3475.75,4209.23 3463.94,4209.23 ccw(c3446.65,4214.9)
  region net $1N6577: 3693.5,3490.84 3683.39,3503.49 ccw(c3678.23,3525.11) 3699.1,3517.44 3721.09,3495.45 ccw(c3720.65,3413.16)
  region net $1N6953: 3412.68,3509.95 3403.23,3497.41 ccw(c3373.66,3422.22) 3376.41,3502.97 3398.4,3524.97 ccw(c3419.39,3530.63)
  region net $1N6577: 3691.53,3506.14 3690.83,3489.97 ccw(c3759.39,3137.21) 3654.98,3481.07 3655.69,3511.85 ccw(c3678.22,3537.94)
  region net $1N6953: 3407.05,3496.02 3407.91,3511.7 ccw(c3422.58,3547.66) 3443.86,3515.17 3444.57,3484.39 ccw(c3200,2761.57)
  region net GND: 3581.62,3988.48 3587.05,4008.05 ccw(c3564.97,4030.13) 3594.94,4021.37 3594.94,3996.37 ccw(c3603.7,3966.4)
  region net PGND: 3533.94,4013.06 3539.37,3993.49 ccw(c3517.29,3971.41) 3526.04,4001.38 3526.04,4026.38 ccw(c3556.02,4035.14)
  region net PGND: 3509.47,3864.38 3519.47,3864.38 ccw(c3538.22,3864.38) 3526.97,3849.38 3501.97,3849.38 ccw(c3490.72,3864.38)
  region net GND: 3603.27,3870.48 3601.42,3858.19 3599.89,3859.29 3597.94,3860.17 3593.52,3861.63 3591.45,3862.41 3589.73,3863.35 3589.06,3863.92 3588.56,3864.55 3588.24,3865.28 3588.12,3866.11 3597.97,3886.39 3598.04,3884.34 3598.27,3882.19 3598.65,3880.01 3599.21,3877.85 3599.94,3875.76 3600.86,3873.8 3601.96,3872.02
  region net CC1: 3435.32,3867.83 3435.32,3877.83 3440.83,3877.95 3443.36,3878.23 3445.64,3878.77 3447.55,3879.66 3448.35,3880.27 3449.03,3881 3449.58,3881.85 3449.99,3882.86 3450.24,3884.01 3450.32,3885.33 3450.32,3866.11 3450.24,3867.36 3449.99,3868.33 3449.58,3869.05 3449.03,3869.54 3448.35,3869.83 3447.55,3869.95 3445.64,3869.78 3440.83,3868.62 3438.12,3868.06
  region net CC2: 3392.02,3838.31 3392.02,3848.31 3407.02,3848.39 3407.02,3838.55 3401.96,3838.43
  region net GND: 3607.76,3851.85 3620.05,3853.7 3621.59,3852.39 3623.37,3851.29 3625.33,3850.37 3627.42,3849.64 3629.59,3849.08 3631.77,3848.7 3633.91,3848.47 3635.96,3848.39 3615.68,3838.55 3614.85,3838.66 3614.13,3838.99 3613.49,3839.49 3612.93,3840.16 3611.98,3841.88 3611.2,3843.95 3609.74,3848.37 3608.86,3850.32
  region net PGND: 3509.47,3840.62 3519.47,3830.69 3519.49,3826.47 3519.84,3822.28 3505.41,3832.22 3506.64,3832.66 3507.6,3833.34 3508.31,3834.24 3508.82,3835.31 3509.16,3836.52 3509.36,3837.84
  region net DN: 3760.88,4029.75 3750.88,4018.46 3750.79,4021.36 3750.62,4022.71 3750.31,4023.94 3749.81,4025.02 3749.1,4025.89 3748.11,4026.52 3746.82,4026.87 3760.4,4038.15 3760.39,4035.66 3760.56,4033.95 3760.77,4032.24
  region net DP: 3716.43,4009.64 3706.43,4009.64 3706.34,4010.77 3706.08,4011.91 3705.18,4014.12 3703.89,4016.2 3702.42,4018.04 3720.43,4018.04 3718.96,4016.2 3717.68,4014.12 3716.77,4011.91 3716.52,4010.77
  region net VDET: 3677.44,4028.89 3667.44,4028.89 3667.35,4030.03 3667.1,4031.17 3666.19,4033.38 3664.91,4035.45 3663.44,4037.3 3681.45,4037.3 3679.98,4035.45 3678.69,4033.38 3677.79,4031.17 3677.53,4030.03
  region net CC1: 3382.72,3893.71 3375.65,3886.64 3374.78,3887.38 3373.8,3888 3371.59,3888.93 3369.22,3889.48 3366.87,3889.75 3379.61,3902.49 3379.87,3900.14 3380.43,3897.77 3381.35,3895.56 3381.98,3894.58
  region net CC2: 3357.7,3855.78 3350.63,3848.71 3349.76,3849.45 3348.78,3850.08 3346.57,3851 3344.2,3851.56 3341.85,3851.82 3354.59,3864.56 3354.85,3862.21 3355.41,3859.84 3356.34,3857.63 3356.96,3856.65
  region net DN: 3533.9,4243.77 3523.9,4243.54 3523.8,4244.67 3523.55,4245.81 3522.63,4248.03 3521.33,4250.11 3519.84,4251.94 3537.85,4252.17 3536.4,4250.32 3535.13,4248.25 3534.24,4246.04 3533.98,4244.91
  region net CC2: 3452.61,4340.26 3448.61,4330.1 3447.75,4330.82 3446.7,4331.44 3444.27,4332.36 3441.69,4332.81 3440.46,4332.83 3439.33,4332.71 3448.61,4348.15 3449.32,4346.01 3450.15,4343.93 3451.22,4341.98
  region net CC1: 3622.76,4333.05 3620.47,4321.2 3619.57,4321.96 3618.51,4322.62 3616.04,4323.6 3614.73,4323.88 3613.44,4324.01 3612.21,4323.95 3611.08,4323.7 3618.11,4340.28 3620.16,4336.46 3621.38,4334.65
  region net VDET: 3395.05,4066.83 3395.05,4081.83 3397.42,4081.76 3399.56,4081.75 3400.57,4081.89 3401.55,4082.17 3402.51,4082.64 3403.45,4083.34 3403.45,4065.33 3402.51,4066.03 3401.55,4066.5 3400.57,4066.78 3399.56,4066.91 3397.42,4066.91
  region net $1N1650: 3264.17,3725.58 3264.17,3715.58 3263.04,3715.49 3261.9,3715.23 3259.69,3714.33 3257.61,3713.04 3255.77,3711.57 3255.77,3729.58 3257.61,3728.11 3259.69,3726.83 3261.9,3725.92 3263.04,3725.67
  region net $1N1651: 3268.06,3679.12 3268.06,3669.12 3266.92,3669.03 3265.79,3668.77 3263.57,3667.87 3261.5,3666.58 3259.66,3665.11 3259.66,3683.12 3261.5,3681.65 3263.57,3680.37 3265.79,3679.46 3266.92,3679.21
Bottom Layer:
  region net PAD1: 3184.01,3067.82 3570.84,3067.82 ccw(c3571.57,3092.78) 3595.98,3087.5 3595.98,3319.22 ccw(c3572.1,3313.86) 3570.84,3338.3 3184.33,3338.3 ccw(c3184.33,3318.3) 3164.33,3318.3 3164.33,3087.5 ccw(c3184.01,3087.5)
  region net LX2: 3625.28,3087.33 3625.28,3318.01 cw(c3644.97,3318.01) 3644.97,3337.7 3784.42,3337.7 cw(c3784.42,3318.01) 3797.93,3332.33 3901.64,3234.42 cw(c3888.13,3220.1) 3907.82,3220.1 3907.82,3087.33 cw(c3888.13,3087.33) 3888.13,3067.65 3644.97,3067.65 cw(c3644.97,3087.33)
  region net PGND: 3452.97,3543.74 3906.4,3541.79 ccw(c3906.49,3561.79) 3920.73,3547.75 3971.74,3599.49 ccw(c3957.5,3613.53) 3977.5,3613.53 3977.5,3902.49 ccw(c3957.82,3902.49) 3970.56,3917.5 3901.28,3976.29 ccw(c3888.54,3961.28) 3888.54,3980.97 3484.37,3981 ccw(c3484.37,3961.31) 3472.15,3976.75 3420.11,3935.54 ccw(c3432.33,3920.1) 3412.64,3920.1 3412.64,3583.19 ccw(c3432.33,3583.19) 3419.72,3568.07 3439.18,3549.33 ccw(c3453.05,3563.74)
  region net DN: 3743.41,4055.12 3753.41,4055.12 3753.5,4053.98 3753.76,4052.85 3754.66,4050.63 3755.95,4048.56 3757.42,4046.71 3739.41,4046.71 3740.88,4048.56 3742.16,4050.63 3743.07,4052.85 3743.32,4053.98
  region net DP: 3706.43,4042.33 3716.43,4042.33 3716.52,4041.19 3716.77,4040.06 3717.68,4037.84 3718.96,4035.77 3720.43,4033.93 3702.42,4033.93 3703.89,4035.77 3705.18,4037.84 3706.08,4040.06 3706.34,4041.19
  region net VDET: 3655.58,4051.5 3666.18,4062.1 3667.81,4060.37 3669.32,4058.86 3670.13,4058.24 3671.02,4057.74 3672.03,4057.4 3673.19,4057.23 3660.46,4044.49 3660.28,4045.65 3659.94,4046.66 3659.45,4047.55 3658.83,4048.36 3657.31,4049.87
  region net CC1: 3362.62,3918.08 3372.62,3918.08 3372.71,3916.94 3372.97,3915.81 3373.87,3913.6 3375.16,3911.52 3376.63,3909.68 3358.62,3909.68 3360.09,3911.52 3361.37,3913.6 3362.28,3915.81 3362.53,3916.94
  region net CC2: 3333.74,3876.84 3343.74,3882.63 3343.85,3881.52 3344.15,3880.33 3345.24,3877.9 3346.79,3875.73 3347.67,3874.87 3348.58,3874.23 3331.52,3868.43 3333.05,3872.55 3333.55,3874.68
  region net DN: 3603.39,4288.28 3618.04,4287.77 3620.92,4284.69 3622.45,4283.09 3623.91,4281.74 3606.46,4279.46 3607.08,4280.63 3607.31,4281.78 3607.19,4282.92 3606.79,4284.03 3606.15,4285.12 3605.33,4286.19
  region net DN: 3523.74,4276.35 3533.74,4276.35 3533.83,4275.21 3534.08,4274.08 3534.99,4271.86 3536.28,4269.79 3537.75,4267.94 3519.73,4267.94 3521.21,4269.79 3522.49,4271.86 3523.4,4274.08 3523.65,4275.21
  region net DN: 3533.74,4243.65 3523.74,4243.65 3523.65,4244.79 3523.4,4245.92 3522.49,4248.14 3521.21,4250.21 3519.73,4252.06 3537.75,4252.06 3536.28,4250.21 3534.99,4248.14 3534.08,4245.92 3533.83,4244.79
  region net DP: 3483.74,4253.65 3473.74,4253.65 3473.65,4254.79 3473.4,4255.92 3472.49,4258.14 3471.21,4260.21 3469.73,4262.06 3487.75,4262.06 3486.28,4260.21 3484.99,4258.14 3484.08,4255.92 3483.83,4254.79
  region net CC2: 3433.76,4329.05 3422.94,4332.37 3423.65,4333.23 3424.27,4334.28 3425.21,4336.76 3425.65,4339.38 3425.65,4340.6 3425.49,4341.71 3441.41,4333.29 3439.35,4332.48 3437.34,4331.56 3435.45,4330.44
  region net CC1: 3590.94,4330.09 3590.94,4340.09 3592.07,4340.18 3593.21,4340.44 3595.42,4341.35 3597.5,4342.63 3599.34,4344.1 3599.34,4326.09 3597.5,4327.56 3595.42,4328.84 3593.21,4329.75 3592.07,4330
  region net VDET: 3427.23,4082.5 3428.23,4067.5 3425.84,4067.56 3423.67,4067.52 3422.65,4067.35 3421.67,4067.04 3420.73,4066.53 3419.82,4065.78 3418.82,4083.77 3419.81,4083.11 3420.78,4082.68 3421.76,4082.44 3422.75,4082.34 3424.86,4082.4
  region net $1N1650: 3242.82,3736.93 3252.82,3736.93 3252.91,3735.79 3253.17,3734.65 3254.08,3732.44 3255.36,3730.37 3256.83,3728.52 3238.82,3728.52 3240.29,3730.37 3241.57,3732.44 3242.48,3734.65 3242.73,3735.79
  region net $1N1651: 3261.53,3688.91 3267.03,3680.26 3265.65,3678.47 3264.67,3676.39 3264,3674.16 3263.51,3671.89 3252.45,3686.1 3254.82,3686.17 3257.31,3686.65 3259.64,3687.56 3260.66,3688.18
  region net $1N1651: 3238.78,4017.04 3231.75,4009.92 3230.89,4010.66 3229.9,4011.28 3227.69,4012.2 3225.31,4012.76 3222.97,4013.01 3235.65,4025.8 3235.92,4023.46 3236.49,4021.09 3237.41,4018.88 3238.03,4017.9
  region net $1N1650: 3239.81,3977.61 3232.74,3970.54 3231.87,3971.28 3230.89,3971.9 3228.68,3972.83 3226.3,3973.39 3223.96,3973.65 3236.7,3986.39 3236.96,3984.04 3237.52,3981.67 3238.44,3979.46 3239.07,3978.48

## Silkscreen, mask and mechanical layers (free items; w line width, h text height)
Top Silkscreen Layer:
  text "JLCJLCJLCJLC" at 3418.74,4370 h31.5
Bottom Silkscreen Layer:
  lines w20: 3419.28,3958.87 3419.28,4001.11 3458.34,4040.18 ; 3806.79,4087.69 3879.65,4160.55 3879.65,4199.62
  text "GND" at 3726.54,4049.68 h60 r270
  text "PGND" at 3480.52,4008.5 h60 r270
  text "Hardware Design  /  By lpp@lpp.moe" at 3143.9,3802.47 h59.06 r270
  text "Caution Hot" at 3645.56,3408.78 h60
Top Solder Mask Layer:
  region: 3508.78,3666.06 3539.42,3666.06 3539.42,3643.17 3508.78,3643.17
  region: 3548.42,3666.45 3579.06,3666.45 3579.06,3643.55 3548.42,3643.55
  region: 3632.92,3718.22 3632.92,3751.02 3660.17,3751.02 3660.17,3718.22
Bottom Solder Mask Layer:
  region: 3452.97,3543.74 3906.4,3541.79 ccw(c3906.49,3561.79) 3920.73,3547.75 3971.74,3599.49 ccw(c3957.5,3613.53) 3977.5,3613.53 3977.5,3902.49 ccw(c3957.82,3902.49) 3970.56,3917.5 3901.28,3976.29 ccw(c3888.54,3961.28) 3888.54,3980.97 3484.37,3981 ccw(c3484.37,3961.31) 3472.15,3976.75 3420.11,3935.54 ccw(c3432.33,3920.1) 3412.64,3920.1 3412.64,3583.19 ccw(c3432.33,3583.19) 3419.72,3568.07 3439.18,3549.33 ccw(c3453.05,3563.74)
